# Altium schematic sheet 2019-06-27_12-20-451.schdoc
size 372 x 177 mm; SheetNumber: 1; SheetTotal: 1
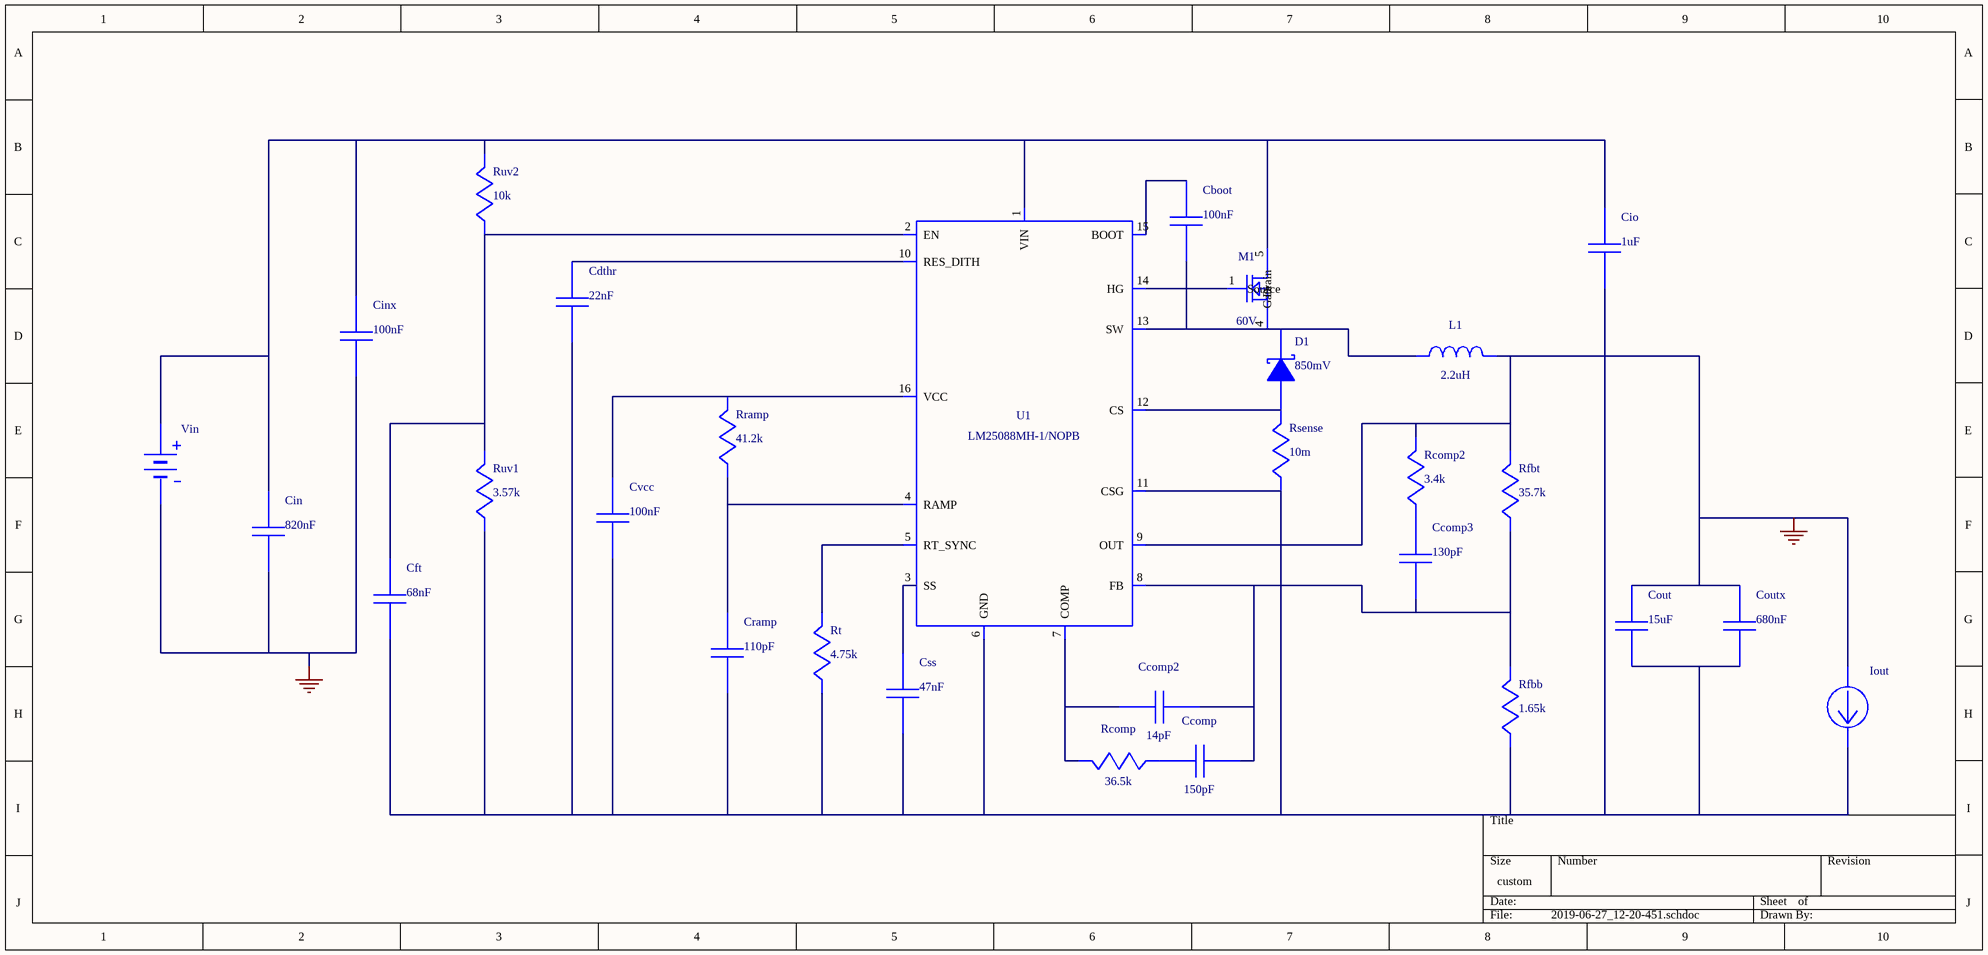
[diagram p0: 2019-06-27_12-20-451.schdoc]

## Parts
Cboot  value 100nF  (hidden comment: CC0805KRX7R9BB104)
Ccomp  value 150pF  (hidden comment: CL21C151JBANNNC)
Ccomp2  value 14pF  (hidden comment: CL21C140JBANNNC)
Ccomp3  value 130pF  (hidden comment: CL21C131JBANNNC)
Cdthr  value 22nF  (hidden comment: GRM216R71H223KA01D)
Cft  value 68nF  (hidden comment: GRM219R71E683KA01D)
Cin  value 820nF  (hidden comment: GRM155R61A824KE15D)
Cinx  value 100nF  (hidden comment: C0805C104M5RACTU)
Cio  value 1uF  (hidden comment: C1608X5R1H105K080AB)
Cout  value 15uF  (hidden comment: C5750X7S2A156M250KB)
Coutx  value 680nF  (hidden comment: C2012X5R1H684K125AB)
Cramp  value 110pF  (hidden comment: CL21C111JBANNNC)
Css  value 47nF  (hidden comment: GRM21BR71H473KA01L)
Cvcc  value 100nF  (hidden comment: CC0805KRX7R9BB104)
D1  value 850mV  (hidden comment: SK310A-TP)
Iout  WB_CURRENT_LOAD  (value not drawn)
L1  value 2.2uH  (hidden comment: 74437346022)
M1  value 60V  (hidden comment: CSD18543Q3A)
Rcomp  value 36.5k  (hidden comment: CRCW080536K5FKEA)
Rcomp2  value 3.4k  (hidden comment: ERJ-6ENF3401V)
Rfbb  value 1.65k  (hidden comment: CRCW08051K65FKEA)
Rfbt  value 35.7k  (hidden comment: CRCW080535K7FKEA)
Rramp  value 41.2k  (hidden comment: CRCW080541K2FKEA)
Rsense  value 10m  (hidden comment: CSR1206FK10L0)
Rt  value 4.75k  (hidden comment: ERJ-6ENF4751V)
Ruv1  value 3.57k  (hidden comment: ERJ-6ENF3571V)
Ruv2  value 10k  (hidden comment: CRCW080510K0FKEA)
U1  LM5088MH-1  (value not drawn)
Vin  WB_BATTERY  (value not drawn)

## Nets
0: Cin.2 Cinx.2 Cout.1 Coutx.1 Iout.1(+) L1.1 Rcomp2.1 Rfbt.1 U1.9(OUT) Vin.2(-)
NetCboot_1: Cboot.1 D1.1(K) L1.2 M1.4(Gate) U1.13(SW)
NetCboot_2: Cboot.2 U1.15(BOOT)
NetCcomp2_1: Ccomp2.1 Rcomp.1 U1.7(COMP)
NetCcomp3_1: Ccomp3.1 Rcomp2.2
NetCcomp_1: Ccomp.1 Rcomp.2
NetCcomp_2: Ccomp.2 Ccomp2.2 Ccomp3.2 Rfbb.1 Rfbt.2 U1.8(FB)
NetCdthr_1: Cdthr.1 U1.10(RES_DITH)
NetCdthr_2: Cdthr.2 Cft.2 Cio.2 Cout.2 Coutx.2 Cramp.2 Css.2 Cvcc.2 Iout.2(-) Rfbb.2 Rsense.2 Rt.2 Ruv1.2 U1.6(GND) U1.11(CSG) U1.17(EP)
NetCft_1: Cft.1 Ruv1.1 Ruv2.2 U1.2(EN)
NetCin_1: Cin.1 Cinx.1 Cio.1 M1.5(Drain) M1.6(Drain) M1.7(Drain) M1.8(Drain) M1.9(Drain) Ruv2.1 U1.1(VIN) Vin.1(+)
NetCramp_1: Cramp.1 Rramp.2 U1.4(RAMP)
NetCss_1: Css.1 U1.3(SS)
NetCvcc_1: Cvcc.1 Rramp.1 U1.16(VCC)
NetD1_2: D1.2(A) Rsense.1 U1.12(CS)
NetM1_1: M1.1(Source) M1.2(Source) M1.3(Source) U1.14(HG)
NetRt_1: Rt.1 U1.5(RT_SYNC)

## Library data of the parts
Cboot Cvcc = CC0805KRX7R9BB104: CC0805KRX7R9BB10; Manufacturer Name: Yageo
Ccomp = CL21C151JBANNNC: Manufacturer Name: Samsung Electro-Mechanics
Ccomp2 = CL21C140JBANNNC: Manufacturer Name: Samsung Electro-Mechanics
Ccomp3 = CL21C131JBANNNC: Manufacturer Name: Samsung Electro-Mechanics
Cdthr = GRM216R71H223KA01D: GRM216R71H223KA0; Manufacturer Name: MuRata
Cft = GRM219R71E683KA01D: GRM219R71E683KA0; Manufacturer Name: MuRata
Cin = GRM155R61A824KE15D: GRM155R61A824KE1; Manufacturer Name: MuRata
Cinx = C0805C104M5RACTU: Manufacturer Name: Kemet
Cio = C1608X5R1H105K080AB: C1608X5R1H105K08; Manufacturer Name: TDK
Cout = C5750X7S2A156M250KB: C5750X7S2A156M25; Manufacturer Name: TDK
Coutx = C2012X5R1H684K125AB: C2012X5R1H684K12; Manufacturer Name: TDK
Cramp = CL21C111JBANNNC: Manufacturer Name: Samsung Electro-Mechanics
Css = GRM21BR71H473KA01L: GRM21BR71H473KA0; Manufacturer Name: MuRata
D1 = SK310A-TP: Manufacturer Name: Micro Commercial Components
L1 = 74437346022: Manufacturer Name: Wurth Elektronik
M1 = CSD18543Q3A: Manufacturer Name: Texas Instruments
Rcomp = CRCW080536K5FKEA: Manufacturer Name: Vishay-Dale
Rcomp2 = ERJ-6ENF3401V: Manufacturer Name: Panasonic
Rfbb = CRCW08051K65FKEA: Manufacturer Name: Vishay-Dale
Rfbt = CRCW080535K7FKEA: Manufacturer Name: Vishay-Dale
Rramp = CRCW080541K2FKEA: Manufacturer Name: Vishay-Dale
Rsense = CSR1206FK10L0: Manufacturer Name: Stackpole Electronics Inc
Rt = ERJ-6ENF4751V: Manufacturer Name: Panasonic
Ruv1 = ERJ-6ENF3571V: Manufacturer Name: Panasonic
Ruv2 = CRCW080510K0FKEA: Manufacturer Name: Vishay-Dale
U1 = LM5088MH-1: LM25088MH-1/NOPB; Manufacturer Name: Texas Instruments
